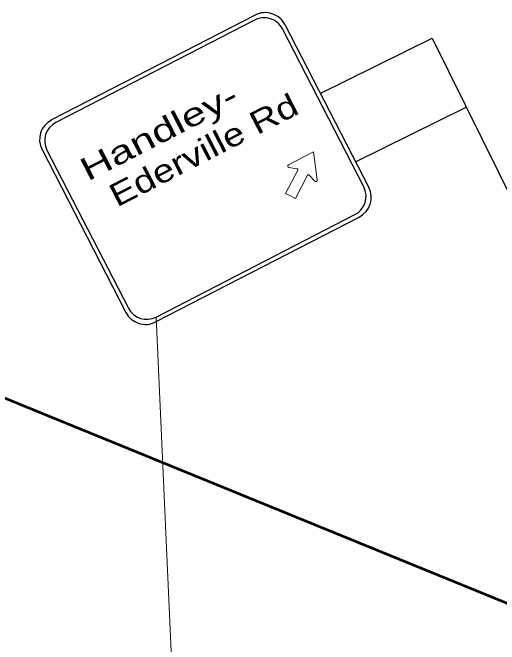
# Model space of a CAD drawing. Extents: x 2356431 to 2371438, y 6972864 to 6982525.
# Drawn here: x 2364327.4 to 2364658.7, y 6979567 to 6979997.1 of the extents above; entities that cross this region are included whole.
import ezdxf
from ezdxf.enums import TextEntityAlignment as Align

# ---------------------------------------------------------------- set-up
doc = ezdxf.new("R2010")
doc.units = 0
doc.header["$LTSCALE"] = 5.6
for name, color, linetype, lineweight in [('1', 7, 'Continuous', 25), ('48', 7, 'Continuous', 25), ('53', 7, 'Continuous', 13)]:
    doc.layers.add(name, color=color, linetype=linetype, lineweight=lineweight)

msp = doc.modelspace()

# ---------------------------------------------------------------- linework, layer by layer
at = {"layer": '1', "lineweight": 53}
msp.add_line((2365578.634, 6979221.374), (2364090.226, 6979829.17), dxfattribs=at)
at = {"layer": '48'}
for p, q in [((2364492.462, 6979995.501), (2364353.852, 6979924.052)), ((2364492.079, 6979992.125), (2364356.807, 6979922.4)), ((2364512.666, 6979989.025), (2364569.792, 6979878.169)), ((2364566.436, 6979878.551), (2364511.021, 6979986.075)), ((2364536.807, 6979942.18), (2364613.004, 6979979.786)), ((2364613.004, 6979979.786), (2364681.289, 6979841.428)), ((2364560.87, 6979895.482), (2364636.251, 6979932.685)), ((2364347.388, 6979903.847), (2364404.528, 6979792.985)), ((2364350.742, 6979903.464), (2364406.163, 6979795.945)), ((2364424.732, 6979786.521), (2364563.338, 6979857.962)), ((2364425.104, 6979789.886), (2364560.377, 6979859.61))]:
    msp.add_line(p, q, dxfattribs=at)
at = {"layer": '48', "lineweight": 13}
msp.add_line((2364437.258, 6979515.664), (2364425.104, 6979789.886), dxfattribs=at)
at = {"layer": '48'}
for centre, radius, start, end in [((2364499.341, 6979982.155), 14.995, 27.26707, 117.26708), ((2364498.534, 6979979.63), 14.057, 27.26708, 117.26708), ((2364360.725, 6979910.711), 14.995, 117.26708, 207.26708), ((2364363.25, 6979909.904), 14.057, 117.26707, 207.26707), ((2364553.955, 6979872.103), 14.057, 297.26707, 27.26707), ((2364556.479, 6979871.296), 14.995, 297.26707, 27.26707), ((2364418.671, 6979802.376), 14.057, 207.26707, 297.26707), ((2364417.863, 6979799.851), 14.995, 207.26708, 297.26708)]:
    msp.add_arc(centre, radius, start, end, dxfattribs=at)
at = {"layer": '53'}
for p, q in [((2364515.515, 6979891.662), (2364520.962, 6979890.905)), ((2364521.518, 6979889.944), (2364521.539, 6979889.927)), ((2364529.309, 6979886.566), (2364533.031, 6979882.437))]:
    msp.add_line(p, q, dxfattribs=at)
for points in [[(2364534.744, 6979883.325), (2364532.244, 6979902.356), (2364515.23, 6979893.584)], [(2364521.539, 6979889.927), (2364513.157, 6979874.106), (2364516.511, 6979872.345), (2364519.947, 6979870.548), (2364528.151, 6979886.415)]]:
    msp.add_lwpolyline(points, dxfattribs=at)
for centre, radius, start, end in [((2364515.673, 6979892.668), 1.012, 117.00557, 262.38671), ((2364520.921, 6979890.258), 0.675, 332.26708, 82.25018), ((2364528.804, 6979886.113), 0.675, 42.28397, 152.26708), ((2364533.765, 6979883.155), 1.012, 222.14744, 7.52858)]:
    msp.add_arc(centre, radius, start, end, dxfattribs=at)

# ---------------------------------------------------------------- texts
at = {"layer": '48'}
for s, width, p in [('Handley-', 1.4, (2364430.573, 6979908.916)), ('Ederville Rd', 1.25, (2364460.957, 6979896.645))]:
    msp.add_text(s, height=15.62, rotation=27.267, dxfattribs=dict(at, width=width)).set_placement(p, align=Align.CENTER)

doc.saveas('drawing.dxf')
